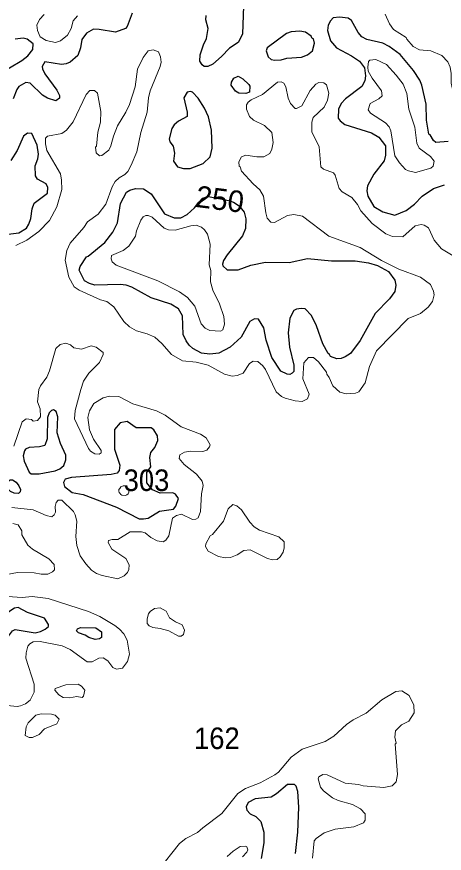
# Model space of a CAD drawing. Extents: x 763.2 to 816.8, y 7896.5 to 7952.7.
# Drawn here: x 807.08 to 810.25, y 7899.66 to 7905.87 of the extents above; entities that cross this region are included whole.
import ezdxf
from ezdxf.enums import TextEntityAlignment as Align

# ---------------------------------------------------------------- set-up
doc = ezdxf.new("R2010")
doc.units = 0
doc.header["$LTSCALE"] = 0.064
doc.layers.add('1', color=7, linetype='Continuous', lineweight=25)
doc.layers.add('2', color=7, linetype='Continuous', lineweight=13)
doc.layers.add('21', color=7, linetype='Continuous')
doc.layers.add('61', color=7, linetype='Continuous')

msp = doc.modelspace()

# ---------------------------------------------------------------- linework, layer by layer
at = {"layer": '1'}
for points in [[(808.764, 7905.9481), (808.7568, 7905.7388), (808.7247, 7905.6775), (808.6593, 7905.6346), (808.6015, 7905.5738), (808.5348, 7905.5156)], [(807.9361, 7905.8945), (807.9009, 7905.7943), (807.8871, 7905.7809), (807.8124, 7905.7543), (807.6934, 7905.7739), (807.6513, 7905.7753), (807.5985, 7905.7452), (807.5645, 7905.6992), (807.554, 7905.6358), (807.5336, 7905.5798), (807.4759, 7905.5311), (807.4482, 7905.5178), (807.4131, 7905.5126), (807.2881, 7905.5331), (807.2703, 7905.4994), (807.2706, 7905.481), (807.2892, 7905.4436), (807.3785, 7905.3235), (807.3978, 7905.2832), (807.398, 7905.2627), (807.3696, 7905.2446), (807.3078, 7905.2621), (807.2715, 7905.2853), (807.1799, 7905.3739), (807.1485, 7905.3807), (807.0971, 7905.3491), (807.0819, 7905.3286), (807.0532, 7905.2594)], [(808.5348, 7905.5156), (808.4993, 7905.4996), (808.4716, 7905.4996), (808.4567, 7905.5111), (808.4406, 7905.5382), (808.4412, 7905.5849), (808.4664, 7905.6603), (808.4893, 7905.7072), (808.5008, 7905.7795), (808.483, 7905.8452), (808.4862, 7905.8774)], [(810.2816, 7904.9422), (810.1916, 7904.9346), (810.1736, 7904.9495), (810.1489, 7904.9898), (810.1395, 7904.9957), (810.1231, 7905.1009), (810.1194, 7905.2184), (810.0873, 7905.3597), (810.0721, 7905.3975), (810.0261, 7905.4698), (809.9258, 7905.5881), (809.8444, 7905.6468), (809.7968, 7905.6721), (809.679, 7905.699), (809.6417, 7905.7181), (809.6153, 7905.7509), (809.5643, 7905.8393), (809.5401, 7905.8568), (809.4763, 7905.8658), (809.428, 7905.8591), (809.4082, 7905.8378), (809.393, 7905.8047), (809.387, 7905.7657), (809.4083, 7905.6902), (809.4531, 7905.6375), (809.565, 7905.5777), (809.6252, 7905.537), (809.6619, 7905.4874), (809.6695, 7905.4302), (809.6641, 7905.3911), (809.6419, 7905.3506), (809.5217, 7905.2577), (809.4888, 7905.2231), (809.4676, 7905.1822), (809.4656, 7905.1159), (809.4806, 7905.0952), (809.5162, 7905.0677), (809.7138, 7905.0054), (809.7679, 7904.9733), (809.8168, 7904.9081), (809.8174, 7904.8405), (809.8075, 7904.797), (809.7308, 7904.6996), (809.6828, 7904.6116), (809.6795, 7904.5757), (809.6861, 7904.5365), (809.7301, 7904.458), (809.797, 7904.4183), (809.8871, 7904.3937), (809.972, 7904.4288), (810.0326, 7904.4773), (810.0903, 7904.5347), (810.175, 7904.5933), (810.2545, 7904.6199)], [(806.9323, 7905.4333), (807.1175, 7905.5429), (807.1631, 7905.5767), (807.2009, 7905.6235), (807.2023, 7905.6669), (807.159, 7905.701), (807.1294, 7905.708), (807.0689, 7905.7012)], [(807.0175, 7904.2545), (807.0958, 7904.262), (807.1532, 7904.2982), (807.171, 7904.327), (807.1856, 7904.3703), (807.1945, 7904.441), (807.2103, 7904.4826), (807.3101, 7904.559), (807.3125, 7904.5988), (807.2998, 7904.6275), (807.2347, 7904.6627), (807.2196, 7904.6869), (807.2178, 7904.7604), (807.2368, 7904.8117), (807.242, 7904.8479), (807.2334, 7904.9147), (807.1914, 7905.0018), (807.161, 7905.0025), (807.1305, 7904.9799), (807.0825, 7904.8745), (807.0359, 7904.8009)], [(808.9147, 7903.5574), (808.8747, 7903.6215), (808.8445, 7903.6256), (808.8108, 7903.6046), (808.7451, 7903.4873), (808.6649, 7903.4153), (808.5799, 7903.3692), (808.5142, 7903.3613), (808.4517, 7903.3707), (808.3879, 7903.4035), (808.3603, 7903.4281), (808.3373, 7903.4619), (808.317, 7903.5084), (808.3116, 7903.6468), (808.2823, 7903.6996), (808.2232, 7903.7342), (808.0771, 7903.7795), (807.9339, 7903.8607), (807.8921, 7903.8738), (807.8473, 7903.879), (807.6594, 7903.8751), (807.6211, 7903.886), (807.5836, 7903.9078), (807.5449, 7903.9852), (807.5509, 7904.0133), (807.5975, 7904.0861), (807.6113, 7904.0903), (807.734, 7904.1917), (807.7947, 7904.2675), (807.8276, 7904.3375), (807.8503, 7904.4804), (807.8942, 7904.5653), (807.9211, 7904.5807), (807.9629, 7904.5935), (808.0208, 7904.5899), (808.0789, 7904.5536), (808.1774, 7904.405), (808.2488, 7904.3753), (808.2994, 7904.3757), (808.3445, 7904.4), (808.3995, 7904.4482), (808.4313, 7904.4906), (808.4604, 7904.5212), (808.5035, 7904.5334), (808.5543, 7904.5241), (808.6292, 7904.508), (808.6627, 7904.5), (808.6894, 7904.492), (808.7309, 7904.4625), (808.7682, 7904.4176), (808.7818, 7904.368), (808.7788, 7904.2948), (808.7551, 7904.2401), (808.6418, 7904.1006), (808.6148, 7904.0571), (808.6067, 7904.03), (808.6096, 7904.019), (808.6425, 7903.9876), (808.7228, 7903.9893), (808.8182, 7904.0235), (808.9266, 7904.0449), (809.1034, 7904.0417), (809.2387, 7904.0727), (809.4165, 7904.0549), (809.5932, 7904.0548), (809.6909, 7904.0402), (809.7582, 7904.0202), (809.8408, 7903.9752), (809.888, 7903.9112), (809.8945, 7903.8749), (809.8859, 7903.8273), (809.848, 7903.7732), (809.7413, 7903.6646), (809.6289, 7903.4633), (809.5582, 7903.3669), (809.5192, 7903.3414), (809.488, 7903.33), (809.4566, 7903.3269), (809.4105, 7903.3447), (809.4031, 7903.3608), (809.3918, 7903.3669), (809.3536, 7903.4392), (809.3048, 7903.5725), (809.2682, 7903.6482), (809.2223, 7903.6978), (809.1922, 7903.7013), (809.1568, 7903.6964), (809.1379, 7903.687), (809.1079, 7903.6299), (809.096, 7903.5215), (809.1041, 7903.413), (809.1366, 7903.2814), (809.1367, 7903.2344), (809.1254, 7903.2201), (809.1071, 7903.2108)], [(809.1071, 7903.2108), (809.0881, 7903.2128), (809.0399, 7903.2352), (808.9744, 7903.3367), (808.9319, 7903.4674), (808.9147, 7903.5574)], [(809.1485, 7899.6553), (809.1665, 7899.8131), (809.1731, 7899.9979), (809.1665, 7900.1147), (809.154, 7900.1537), (809.1427, 7900.1679), (809.0905, 7900.1675), (809.0088, 7900.0975), (808.9695, 7900.073), (808.8511, 7900.0594), (808.7971, 7900.0325), (808.7824, 7899.9999), (808.7874, 7899.9753), (808.8121, 7899.9488), (808.8559, 7899.928), (808.8919, 7899.8918), (808.9151, 7899.8125), (808.9134, 7899.7342), (808.894, 7899.6176)]]:
    msp.add_lwpolyline(points, dxfattribs=at)
for points in [[(809.1936, 7905.5687), (809.2381, 7905.5862), (809.2746, 7905.6143), (809.2895, 7905.6718), (809.2829, 7905.7028), (809.2732, 7905.7073), (809.2649, 7905.7241), (809.2239, 7905.7522), (809.1815, 7905.7604), (809.1183, 7905.7555), (809.0834, 7905.7444), (808.9403, 7905.6372), (808.9319, 7905.6135), (808.946, 7905.569), (808.9679, 7905.5506), (808.9974, 7905.5451), (809.0442, 7905.547), (809.0852, 7905.5602)], [(808.6721, 7905.3596), (808.6749, 7905.383), (808.6929, 7905.4115), (808.7237, 7905.4263), (808.7595, 7905.4079), (808.8025, 7905.3635), (808.8099, 7905.3515), (808.8085, 7905.3085), (808.7812, 7905.2974), (808.7288, 7905.2993), (808.7033, 7905.3154)], [(808.5042, 7905.1247), (808.475, 7905.1897), (808.4269, 7905.2627), (808.3862, 7905.3076), (808.3711, 7905.3133), (808.346, 7905.3077), (808.3208, 7905.2667), (808.3462, 7905.1582), (808.3461, 7905.1283), (808.2803, 7905.0924), (808.2492, 7905.0664), (808.2313, 7905.0368), (808.2121, 7904.962), (808.2172, 7904.9385), (808.241, 7904.9058), (808.251, 7904.8559), (808.2432, 7904.7956), (808.2744, 7904.7527), (808.3186, 7904.7402), (808.3685, 7904.7403), (808.4638, 7904.7784), (808.5154, 7904.8275), (808.5304, 7904.893), (808.5272, 7905.0261)], [(807.4442, 7902.5781), (807.444, 7902.6116), (807.4046, 7902.6997), (807.3804, 7902.7771), (807.3845, 7902.8979), (807.3734, 7902.9354), (807.3533, 7902.9481), (807.3375, 7902.9436), (807.3212, 7902.9273), (807.3084, 7902.8913), (807.3061, 7902.7326), (807.2896, 7902.6848), (807.2496, 7902.6744), (807.1732, 7902.6696), (807.1453, 7902.6561), (807.1371, 7902.6446), (807.1289, 7902.6069), (807.1352, 7902.5683), (807.1718, 7902.487), (807.1887, 7902.474), (807.2463, 7902.4739), (807.3647, 7902.4951), (807.4008, 7902.5097), (807.4312, 7902.5353)], [(808.0463, 7902.4827), (808.075, 7902.5265), (808.0689, 7902.5938), (808.0753, 7902.6324), (808.1044, 7902.6704), (808.1271, 7902.7201), (808.1261, 7902.7553), (808.0971, 7902.8001), (808.0785, 7902.8154), (807.9666, 7902.8155), (807.9001, 7902.8611), (807.8481, 7902.8512), (807.8058, 7902.8025), (807.8073, 7902.658), (807.845, 7902.5387), (807.8403, 7902.4993), (807.8253, 7902.479), (807.7815, 7902.4686), (807.4863, 7902.4473), (807.4388, 7902.433), (807.4284, 7902.4093), (807.4356, 7902.3806), (807.493, 7902.3346), (807.5731, 7902.3206), (807.8219, 7902.2269), (807.99, 7902.1403), (808.022, 7902.1386), (808.0556, 7902.1453), (808.1401, 7902.1962), (808.2451, 7902.2121), (808.2617, 7902.2323), (808.2806, 7902.2907), (808.2595, 7902.3236), (808.2403, 7902.3321), (808.1449, 7902.3309), (808.0886, 7902.3557), (808.0459, 7902.4065)], [(807.0337, 7902.3425), (807.0106, 7902.3672), (807.0072, 7902.4024), (807.0308, 7902.4285), (807.0491, 7902.4293), (807.0769, 7902.4118), (807.0969, 7902.3855), (807.1084, 7902.3574), (807.1057, 7902.3398), (807.0931, 7902.3281), (807.0625, 7902.3308)], [(807.0491, 7901.3071), (807.0696, 7901.3165), (807.2181, 7901.2925), (807.2569, 7901.3022), (807.2923, 7901.3199), (807.3153, 7901.341), (807.3174, 7901.3547), (807.2857, 7901.4008), (807.1599, 7901.443), (807.0915, 7901.4818), (807.0641, 7901.4772), (807.0217, 7901.4492), (806.9367, 7901.2921), (806.949, 7901.2555), (806.9674, 7901.2462), (806.9848, 7901.2466), (807.0113, 7901.2591)], [(807.6665, 7901.331), (807.7087, 7901.2995), (807.7105, 7901.2591), (807.695, 7901.2474), (807.6628, 7901.243), (807.6152, 7901.2572), (807.5896, 7901.2758), (807.5385, 7901.292), (807.5237, 7901.3089), (807.5312, 7901.3231), (807.5529, 7901.333)]]:
    msp.add_lwpolyline(points, close=True, dxfattribs=at)
at = {"layer": '2'}
for points in [[(807.2831, 7905.8857), (807.2484, 7905.8471), (807.2309, 7905.8049), (807.2356, 7905.7657), (807.254, 7905.7182), (807.2978, 7905.6918), (807.3692, 7905.6755), (807.4046, 7905.6885), (807.4574, 7905.7301), (807.4837, 7905.7812), (807.4986, 7905.8379), (807.531, 7905.8748)], [(809.814, 7905.886), (809.848, 7905.8155), (809.8765, 7905.7741), (809.9704, 7905.7141), (809.9749, 7905.7017), (810.0234, 7905.647), (810.0705, 7905.6227), (810.153, 7905.6157), (810.2352, 7905.5792), (810.2808, 7905.5327), (810.2963, 7905.494), (810.3053, 7905.4476), (810.304, 7905.3739), (810.3206, 7905.3072), (810.3651, 7905.2621), (810.4216, 7905.2335), (810.4602, 7905.2013), (810.4941, 7905.1417)], [(809.9174, 7903.9933), (810.0777, 7903.9328), (810.1504, 7903.8807), (810.174, 7903.8307), (810.1787, 7903.8035), (810.1654, 7903.753), (810.1331, 7903.7103), (810.0779, 7903.6643), (809.9851, 7903.6274), (809.7501, 7903.3882), (809.6993, 7903.2698), (809.6658, 7903.1486), (809.6194, 7903.0817), (809.5954, 7903.0726), (809.5256, 7903.067), (809.4795, 7903.0801), (809.4265, 7903.1267), (809.3996, 7903.1901), (809.3821, 7903.2135), (809.38, 7903.228), (809.3205, 7903.3042), (809.2841, 7903.3365), (809.2466, 7903.3375), (809.2123, 7903.2972), (809.2029, 7903.1796), (809.2518, 7903.0647), (809.2381, 7903.0307), (809.1987, 7903.0097), (809.1462, 7903.0147), (809.074, 7903.0352), (809.0467, 7903.0491), (809.0064, 7903.0833), (808.9257, 7903.2492), (808.9074, 7903.2754), (808.8707, 7903.3084), (808.836, 7903.3104), (808.8089, 7903.2923), (808.7622, 7903.2202), (808.7156, 7903.2033), (808.6805, 7903.1985), (808.6229, 7903.214), (808.5019, 7903.2809), (808.4113, 7903.3019), (808.3106, 7903.3126), (808.2296, 7903.3586), (808.1575, 7903.4418), (808.1043, 7903.4881), (808.049, 7903.5141), (807.9702, 7903.5355), (807.9177, 7903.5651), (807.8749, 7903.6046), (807.8002, 7903.7133), (807.75, 7903.7522), (807.7015, 7903.7649), (807.5443, 7903.8371), (807.5069, 7903.8629), (807.466, 7903.9342), (807.4395, 7904.0597), (807.4523, 7904.1313), (807.4775, 7904.186), (807.5787, 7904.3039), (807.6061, 7904.3446), (807.6837, 7904.4011), (807.7406, 7904.4754), (807.7891, 7904.6046), (807.8113, 7904.6451), (807.8416, 7904.6722), (807.8824, 7904.6955), (807.9046, 7904.7196), (807.9308, 7904.7655), (807.9726, 7904.8659), (808.0004, 7905.0087), (808.0484, 7905.1582), (808.0589, 7905.2653), (808.0703, 7905.3179), (808.1454, 7905.498), (808.1523, 7905.5307), (808.1473, 7905.5691), (808.1316, 7905.6083), (808.0934, 7905.6221), (808.0562, 7905.6147), (808.019, 7905.5648), (807.9757, 7905.4777), (807.9584, 7905.3475), (807.9175, 7905.2168), (807.8912, 7905.1582), (807.8289, 7905.0589), (807.7979, 7904.9807), (807.7785, 7904.9086), (807.7636, 7904.876), (807.7127, 7904.838), (807.6954, 7904.8356), (807.6708, 7904.8584), (807.6662, 7904.8999), (807.6726, 7904.9067)], [(810.3197, 7904.0928), (810.2335, 7904.1451), (810.1783, 7904.2095), (810.1362, 7904.3006), (810.1048, 7904.3209), (810.0829, 7904.3242), (810.0384, 7904.3162), (809.9474, 7904.2328), (809.8706, 7904.2363), (809.8201, 7904.2557), (809.7192, 7904.332), (809.635, 7904.4256), (809.6098, 7904.4745), (809.5677, 7904.5258), (809.4959, 7904.5688), (809.4729, 7904.5918), (809.4438, 7904.6924), (809.4324, 7904.7086), (809.3563, 7904.7358), (809.338, 7904.7545), (809.3243, 7904.9011), (809.2705, 7905.0122), (809.2718, 7905.0845), (809.2815, 7905.1191), (809.3621, 7905.1971), (809.3882, 7905.2488), (809.3965, 7905.3014), (809.3802, 7905.3621), (809.3591, 7905.3773), (809.3238, 7905.3788), (809.3003, 7905.3683), (809.2594, 7905.3205), (809.1964, 7905.2058), (809.1574, 7905.1858), (809.146, 7905.1865), (809.1116, 7905.2226), (809.0941, 7905.2632), (809.0771, 7905.3463), (809.0627, 7905.3745), (809.0441, 7905.3857), (809.0157, 7905.3825), (808.9042, 7905.2911), (808.8209, 7905.2517), (808.7987, 7905.2346), (808.7857, 7905.2133), (808.7856, 7905.1807), (808.8072, 7905.1273), (808.8373, 7905.0996), (808.9207, 7905.06), (808.9745, 7905.0081), (808.984, 7904.9333), (808.9745, 7904.8854), (808.9585, 7904.8512), (808.9153, 7904.8273), (808.8627, 7904.8274), (808.78, 7904.8399), (808.7477, 7904.827), (808.7296, 7904.7894), (808.7326, 7904.7577), (808.7393, 7904.7525), (808.7483, 7904.7215), (808.8352, 7904.6278), (808.886, 7904.5836), (808.9127, 7904.5344), (808.929, 7904.4109), (808.9396, 7904.3718), (808.9668, 7904.3425), (808.9936, 7904.3412), (809.0904, 7904.3929), (809.137, 7904.3998)], [(807.6571, 7905.3201), (807.622, 7905.32), (807.596, 7905.2911), (807.5002, 7905.0874), (807.4487, 7905.0256), (807.4148, 7905), (807.3097, 7904.9815), (807.2934, 7904.9666), (807.2935, 7904.9233), (807.3044, 7904.8756), (807.4045, 7904.7013), (807.4131, 7904.6539), (807.4144, 7904.5852), (807.3782, 7904.4568), (807.3227, 7904.3546), (807.2451, 7904.2729), (807.156, 7904.2086), (807.0734, 7904.1703)], [(807.6726, 7904.9067), (807.6827, 7905.0103), (807.7021, 7905.0845), (807.7054, 7905.1648), (807.681, 7905.3014), (807.6571, 7905.3201)], [(809.137, 7904.3998), (809.2011, 7904.3866), (809.3981, 7904.2381), (809.6294, 7904.1553), (809.7872, 7904.0584), (809.9174, 7903.9933)], [(807.0594, 7902.6786), (807.122, 7902.8597), (807.1496, 7902.8813), (807.189, 7902.8763), (807.2026, 7902.865), (807.2356, 7902.8689), (807.2565, 7902.896), (807.2537, 7902.9555), (807.2341, 7903.008), (807.2455, 7903.0999), (807.2559, 7903.1265), (807.3036, 7903.1918), (807.324, 7903.2374), (807.3704, 7903.4039), (807.4017, 7903.4333), (807.446, 7903.4433), (807.4792, 7903.4308), (807.5035, 7903.409), (807.5603, 7903.3995), (807.6329, 7903.4234), (807.6689, 7903.4149), (807.7222, 7903.3758), (807.7219, 7903.3596), (807.6938, 7903.3006), (807.6152, 7903.2216), (807.5771, 7903.1618), (807.5554, 7903.1009), (807.5152, 7902.9429), (807.5102, 7902.8821), (807.6142, 7902.6627), (807.6286, 7902.6431), (807.6597, 7902.6211), (807.6934, 7902.6186), (807.7072, 7902.6297), (807.7069, 7902.646)], [(807.6519, 7902.995), (807.723, 7903.0388), (807.7696, 7903.0506), (807.8394, 7903.0471), (807.942, 7902.9927), (808.1188, 7902.9403), (808.1832, 7902.9097), (808.3015, 7902.8226), (808.4456, 7902.7682), (808.4866, 7902.7407), (808.5153, 7902.6898), (808.511, 7902.6731), (808.4914, 7902.649), (808.4626, 7902.6383), (808.3711, 7902.6414), (808.3245, 7902.6346), (808.2913, 7902.6154), (808.2859, 7902.5869), (808.3225, 7902.5422), (808.4155, 7902.4705), (808.4558, 7902.4191), (808.4644, 7902.3875), (808.4523, 7902.325), (808.4455, 7902.1943), (808.4277, 7902.1481), (808.411, 7902.1368), (808.3846, 7902.1355), (808.3037, 7902.1729), (808.2668, 7902.165), (808.2373, 7902.1441), (808.2105, 7902.0135), (808.1876, 7901.9799), (808.167, 7901.9695), (808.1233, 7901.975), (808.076, 7902.0002), (808.0331, 7902.0353), (808.0056, 7902.0432), (807.9231, 7902.0441), (807.8302, 7901.9848), (807.7894, 7901.9872), (807.761, 7901.9779), (807.7585, 7901.963), (807.787, 7901.9141), (807.8898, 7901.845), (807.914, 7901.7981), (807.9113, 7901.7636), (807.9018, 7901.7401), (807.878, 7901.7155), (807.8319, 7901.6949), (807.7138, 7901.7179), (807.6737, 7901.733), (807.636, 7901.7578), (807.5929, 7901.8046), (807.5508, 7901.8653), (807.5265, 7901.9405), (807.5199, 7902.0088), (807.5264, 7902.1222), (807.5147, 7902.1702), (807.5023, 7902.194), (807.4142, 7902.2793), (807.3886, 7902.278), (807.3723, 7902.2603), (807.3654, 7902.2316), (807.3686, 7902.1902), (807.3574, 7902.1684), (807.34, 7902.1551), (807.2997, 7902.1633), (807.2036, 7902.2061), (807.0447, 7902.2238)], [(807.7069, 7902.646), (807.6514, 7902.7319), (807.6216, 7902.8015), (807.6087, 7902.8914), (807.6194, 7902.9413), (807.6519, 7902.995)], [(807.0524, 7902.1056), (807.0906, 7902.0937), (807.1184, 7902.0494), (807.1177, 7902.0216), (807.1633, 7901.9431), (807.1982, 7901.9141), (807.318, 7901.842), (807.3587, 7901.8008), (807.3598, 7901.7618), (807.3468, 7901.7471), (807.3125, 7901.7279), (807.2628, 7901.7278), (807.2104, 7901.7391), (807.0855, 7901.7409), (807.0065, 7901.7256)], [(806.9302, 7901.5994), (806.9709, 7901.5749), (807.0111, 7901.5617), (807.1214, 7901.5552), (807.1944, 7901.5617), (807.3128, 7901.5485)], [(807.3128, 7901.5485), (807.6139, 7901.4505), (807.6979, 7901.4134), (807.8091, 7901.348), (807.8441, 7901.3211), (807.8751, 7901.285), (807.901, 7901.2379), (807.9175, 7901.1351), (807.9031, 7901.0793), (807.8659, 7901.0302), (807.8221, 7901.0242), (807.7928, 7901.0363), (807.7575, 7901.0838), (807.7231, 7901.1062), (807.6904, 7901.1044), (807.6415, 7901.0771), (807.6035, 7901.0786), (807.4765, 7901.1693), (807.4169, 7901.1965), (807.2543, 7901.2296), (807.2018, 7901.2263), (807.1777, 7901.2111), (807.1634, 7901.1934), (807.1501, 7901.1442), (807.147, 7901.1049), (807.2108, 7900.9109), (807.2093, 7900.8524), (807.1795, 7900.794), (807.146, 7900.7653), (807.109, 7900.7499), (807.0825, 7900.747), (806.8339, 7900.7703)], [(809.3706, 7900.4851), (809.4344, 7900.5264), (809.5282, 7900.6118), (809.5769, 7900.6475), (809.6748, 7900.6965), (809.7911, 7900.7942), (809.8931, 7900.8564), (809.9377, 7900.8612), (809.9938, 7900.8279), (810.0279, 7900.7558), (810.0307, 7900.6999), (809.9909, 7900.636), (809.9354, 7900.6092), (809.8929, 7900.5661), (809.8865, 7900.5191), (809.8958, 7900.4726), (809.8898, 7900.4658), (809.9077, 7900.2404), (809.8956, 7900.1877), (809.8661, 7900.1575), (809.8058, 7900.1434), (809.6519, 7900.1563), (809.6163, 7900.1664), (809.5177, 7900.1765), (809.3847, 7900.2375), (809.3533, 7900.2401), (809.3226, 7900.2248), (809.3179, 7900.2085), (809.334, 7900.146), (809.3577, 7900.1185), (809.425, 7900.0687), (809.4658, 7900.0473), (809.5728, 7900.019), (809.6327, 7899.986), (809.666, 7899.9488), (809.6661, 7899.9008), (809.6541, 7899.882), (809.5815, 7899.853), (809.4449, 7899.8349), (809.3627, 7899.8088), (809.3025, 7899.7666), (809.2869, 7899.7478), (809.275, 7899.6201)], [(808.9968, 7900.2379), (809.0244, 7900.2594), (809.1179, 7900.369), (809.1983, 7900.4285), (809.3706, 7900.4851)], [(808.461, 7899.8453), (808.604, 7899.9507), (808.7225, 7900.0999), (808.7778, 7900.138), (808.8878, 7900.1798), (808.9968, 7900.2379)], [(808.1266, 7899.5259), (808.2895, 7899.7281), (808.3345, 7899.7661), (808.4221, 7899.8098), (808.461, 7899.8453)], [(808.7562, 7899.6295), (808.7877, 7899.664), (808.7949, 7899.6817), (808.7881, 7899.7033), (808.7773, 7899.7095), (808.7383, 7899.7052), (808.686, 7899.6729), (808.6429, 7899.6328)]]:
    msp.add_lwpolyline(points, dxfattribs=at)
for points in [[(809.8168, 7905.0791), (809.7052, 7905.1518), (809.688, 7905.1778), (809.703, 7905.2233), (809.7691, 7905.2575), (809.7927, 7905.2804), (809.7876, 7905.3184), (809.7184, 7905.4112), (809.689, 7905.4635), (809.6853, 7905.4922), (809.6911, 7905.5348), (809.701, 7905.5452), (809.7456, 7905.55), (809.8239, 7905.5125), (809.8979, 7905.4352), (809.9484, 7905.3668), (809.9762, 7905.2978), (809.9918, 7905.1806), (810.0343, 7905.0491), (810.05, 7904.9285), (810.0672, 7904.8931), (810.1509, 7904.8305), (810.1787, 7904.7959), (810.1709, 7904.7573), (810.1537, 7904.7435), (810.0396, 7904.7123), (809.9873, 7904.723), (809.9664, 7904.7341), (809.9205, 7904.7834), (809.8879, 7904.8361), (809.8572, 7905.0217), (809.8459, 7905.0497)], [(808.1276, 7903.9067), (807.8185, 7904.024), (807.7893, 7904.0484), (807.7812, 7904.0706), (807.7833, 7904.094), (807.8715, 7904.1321), (807.9133, 7904.164), (807.9611, 7904.2392), (807.9699, 7904.2793), (808.0027, 7904.3582), (808.0186, 7904.3809), (808.0381, 7904.3911), (808.0567, 7904.3913), (808.086, 7904.3794), (808.1752, 7904.2975), (808.2068, 7904.2866), (808.2575, 7904.2835), (808.373, 7904.3158), (808.4132, 7904.321), (808.4512, 7904.3053), (808.4734, 7904.2861), (808.4967, 7904.2535), (808.5156, 7904.1787), (808.5093, 7904.0247), (808.5223, 7903.9828), (808.5193, 7903.9006), (808.5351, 7903.8376), (808.5857, 7903.7355), (808.6187, 7903.6412), (808.6226, 7903.5839), (808.6108, 7903.5421), (808.5934, 7903.5322), (808.5145, 7903.5376), (808.4798, 7903.5552), (808.4502, 7903.5867), (808.4024, 7903.7179), (808.3491, 7903.7842), (808.289, 7903.8263)], [(807.8618, 7902.316), (807.8533, 7902.3192), (807.8458, 7902.3289), (807.841, 7902.3353), (807.8388, 7902.3438), (807.8394, 7902.3561), (807.8452, 7902.3647), (807.8533, 7902.3759), (807.8597, 7902.3802), (807.8704, 7902.3845), (807.8816, 7902.3839), (807.8944, 7902.3775), (807.9051, 7902.3679), (807.9105, 7902.3594), (807.9126, 7902.3481), (807.9126, 7902.3364), (807.9083, 7902.3262), (807.8976, 7902.3171), (807.8869, 7902.3128)], [(808.8833, 7902.0551), (808.8439, 7902.0798), (808.81, 7902.114), (808.7491, 7902.2059), (808.7151, 7902.2366), (808.6835, 7902.2451), (808.6505, 7902.2141), (808.6148, 7902.1215), (808.5343, 7902.0225), (808.5169, 7902.0132), (808.4835, 7901.9542), (808.4815, 7901.9334), (808.5022, 7901.8994), (808.5777, 7901.8597), (808.6308, 7901.851), (808.667, 7901.8526), (808.7157, 7901.8721), (808.765, 7901.9048), (808.812, 7901.9084), (808.9412, 7901.8439), (808.9786, 7901.8347), (809.0123, 7901.8376), (809.0355, 7901.8581), (809.0586, 7901.8918), (809.0658, 7901.923), (809.0649, 7901.9681), (809.0251, 7902.0054)], [(808.3079, 7901.3524), (808.2595, 7901.3744), (808.2154, 7901.4051), (808.1902, 7901.4547), (808.1451, 7901.4775), (808.104, 7901.4745), (808.07, 7901.4525), (808.0582, 7901.4349), (808.0475, 7901.3973), (808.0494, 7901.3625), (808.0628, 7901.3437), (808.0919, 7901.3315), (808.1444, 7901.3249), (808.2094, 7901.3071), (808.2801, 7901.2677), (808.3012, 7901.2692), (808.3187, 7901.2805), (808.3265, 7901.3119)], [(807.5619, 7900.8963), (807.5357, 7900.9125), (807.4449, 7900.9059), (807.365, 7900.8784), (807.3638, 7900.8678), (807.3939, 7900.8317), (807.4252, 7900.8121), (807.4728, 7900.8091), (807.5269, 7900.8206), (807.567, 7900.8125), (807.5759, 7900.8215), (807.5854, 7900.8683)], [(807.2872, 7900.5803), (807.377, 7900.6171), (807.3949, 7900.6526), (807.3669, 7900.6807), (807.3391, 7900.689), (807.2618, 7900.6907), (807.2225, 7900.6821), (807.1651, 7900.6249), (807.1513, 7900.5939), (807.143, 7900.5317), (807.1733, 7900.5155), (807.1985, 7900.5151), (807.2464, 7900.5392)]]:
    msp.add_lwpolyline(points, close=True, dxfattribs=at)

# ---------------------------------------------------------------- texts
at = {"layer": '21', "width": 0.95}
for s, p in [('303', (807.874, 7902.3461)), ('162', (808.3962, 7900.4299))]:
    msp.add_text(s, height=0.16, dxfattribs=at).set_placement(p)
at = {"layer": '61'}
msp.add_text('250', height=0.16, rotation=352.722, dxfattribs=at).set_placement((808.5783, 7904.4338), align=Align.CENTER)

doc.saveas('drawing.dxf')
